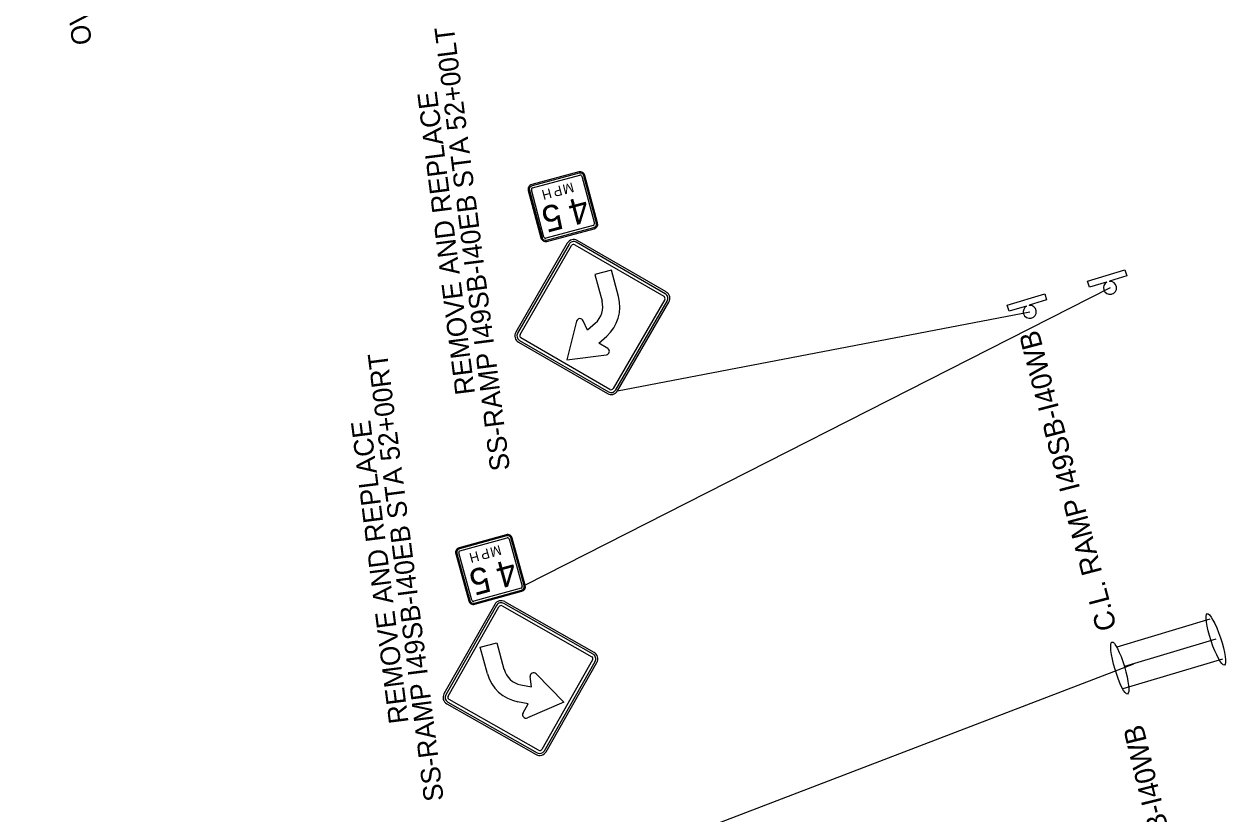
# Model space of a CAD drawing. Extents: x 639753 to 654136, y 407791 to 434220.
# Drawn here: x 643579 to 644317, y 427561 to 428045 of the extents above; entities that cross this region are included whole.
import ezdxf

# ---------------------------------------------------------------- set-up
doc = ezdxf.new("R2010")
doc.units = 0
for name, color, linetype in [('C-TRAF-SYMB', 7, 'Continuous'), ('R_Anno_Text', 7, 'Continuous'), ('R_Draft', 7, 'Continuous'), ('S_SIGN', 7, 'Continuous')]:
    doc.layers.add(name, color=color, linetype=linetype)

msp = doc.modelspace()

# ---------------------------------------------------------------- linework, layer by layer
at = {"layer": 'C-TRAF-SYMB'}
for p, q in [((644231.04, 427887.93), (644254.02, 427894.85)), ((644254.02, 427894.85), (644255.18, 427891.02)), ((644232.2, 427884.1), (644231.04, 427887.93)), ((644242.77, 427887.28), (644232.2, 427884.1)), ((644242.8, 427887.17), (644242.77, 427887.28)), ((644255.18, 427891.02), (644244.5, 427887.8)), ((644244.5, 427887.8), (644244.53, 427887.71)), ((644181.86, 427873.21), (644204.84, 427880.13)), ((644204.84, 427880.13), (644205.99, 427876.3)), ((644183.01, 427869.38), (644181.86, 427873.21)), ((644193.58, 427872.56), (644183.01, 427869.38)), ((644193.62, 427872.45), (644193.58, 427872.56)), ((644205.99, 427876.3), (644195.32, 427873.08)), ((644195.32, 427873.08), (644195.35, 427872.99)), ((644305.99, 427680.53), (644248.98, 427663.47)), ((644309.66, 427668.26), (644253.68, 427651.51)), ((644313.83, 427656.15), (644252.65, 427637.84))]:
    msp.add_line(p, q, dxfattribs=at)
for centre, start, end in [((644244.84, 427883.73), 120.62154, 196.75942), ((644244.84, 427883.73), 196.75942, 94.43951), ((644195.65, 427869.01), 120.62154, 196.75942), ((644195.65, 427869.01), 196.75942, 94.43951)]:
    msp.add_arc(centre, 4, start, end, dxfattribs=at)
for centre, major_axis in [((644309.66, 427668.26), (5.27, -15.78)), ((644250.81, 427650.65), (4.77, -15.94))]:
    msp.add_ellipse(centre, major_axis=major_axis, ratio=0.180134, dxfattribs=at)
at = {"layer": 'S_SIGN'}
for p, q in [((643919.39, 427954.76), (643890.41, 427947.03)), ((643930.79, 427923.64), (643923.06, 427952.63)), ((643888.28, 427943.35), (643896.01, 427914.37)), ((643899.68, 427912.24), (643928.67, 427919.97)), ((643912.21, 427911.11), (643880.65, 427856.59)), ((643972.88, 427881.19), (643918.36, 427912.75)), ((643939.32, 427894.57), (643929.18, 427891.86)), ((643943.65, 427878.33), (643939.32, 427894.57)), ((643929.18, 427891.86), (643933.51, 427875.62)), ((644244.84, 427883.73), (643886.49, 427701.37)), ((643942.96, 427820.52), (643974.52, 427875.04)), ((643917.94, 427863.25), (643912.04, 427839.67)), ((643924.52, 427857.72), (643921.95, 427863.59)), ((643942.96, 427820.52), (644195.65, 427869.01)), ((643929.41, 427862.03), (643924.52, 427857.72)), ((643882.29, 427850.44), (643936.81, 427818.88)), ((643931.48, 427849.85), (643936.36, 427854.17)), ((643936.99, 427846.58), (643931.48, 427849.85)), ((643912.04, 427839.67), (643936.16, 427842.64)), ((643874.83, 427732.39), (643845.91, 427724.42)), ((643886.49, 427701.37), (643878.52, 427730.29)), ((643843.82, 427720.73), (643851.79, 427691.81)), ((643855.47, 427689.71), (643884.4, 427697.68)), ((643867.75, 427689.65), (643836.64, 427634.87)), ((643928.67, 427660.23), (643873.88, 427691.34)), ((643858.84, 427663.37), (643868.97, 427666.16)), ((643868.97, 427666.16), (643873.43, 427649.96)), ((643863.31, 427647.17), (643858.84, 427663.37)), ((643899.24, 427599.31), (643930.36, 427654.09)), ((643997.17, 427552.78), (644259.53, 427653.26)), ((643890.23, 427639.04), (643889.48, 427645.4)), ((643893.11, 427647.14), (643910.12, 427629.77)), ((643883.83, 427640.3), (643890.23, 427639.04)), ((643838.33, 427628.73), (643893.11, 427597.62)), ((643888.2, 427628.74), (643881.8, 427630)), ((643885.09, 427623.13), (643888.2, 427628.74)), ((643910.12, 427629.77), (643887.79, 427620.15))]:
    msp.add_line(p, q, dxfattribs=at)
for points in [[(643919.59, 427954.03), (643890.6, 427946.3)], [(643890.92, 427945.09), (643919.91, 427952.82)], [(643919.59, 427954.03), (643919.59, 427954.03), (643919.59, 427954.03)], [(643921.13, 427952.11), (643928.86, 427923.13)], [(643930.07, 427923.45), (643922.34, 427952.44)], [(643889, 427943.55), (643896.73, 427914.56)], [(643889, 427943.55), (643889, 427943.55), (643889, 427943.55)], [(643897.94, 427914.88), (643890.21, 427943.87)], [(643930.07, 427923.45), (643930.07, 427923.45), (643930.07, 427923.45)], [(643928.15, 427921.9), (643899.17, 427914.17)], [(643899.49, 427912.97), (643928.47, 427920.7)], [(643913.29, 427910.49), (643881.73, 427855.97)], [(643883.24, 427855.09), (643914.81, 427909.61)], [(643899.49, 427912.97), (643899.49, 427912.97), (643899.49, 427912.97)], [(643913.29, 427910.49), (643913.29, 427910.49), (643913.29, 427910.49)], [(643916.86, 427910.16), (643971.38, 427878.59)], [(643972.26, 427880.1), (643917.73, 427911.67)], [(643972.26, 427880.1), (643972.26, 427880.1), (643972.26, 427880.1)], [(643971.93, 427876.54), (643940.36, 427822.02)], [(643941.87, 427821.14), (643973.44, 427875.66)], [(643882.91, 427851.53), (643937.43, 427819.96)], [(643882.91, 427851.53), (643882.91, 427851.53), (643882.91, 427851.53)], [(643938.31, 427821.47), (643883.79, 427853.04)], [(643941.87, 427821.14), (643941.87, 427821.14), (643941.87, 427821.14)], [(643875.03, 427731.66), (643846.11, 427723.69)], [(643846.44, 427722.49), (643875.36, 427730.46)], [(643875.03, 427731.66), (643875.03, 427731.66), (643875.03, 427731.66)], [(643876.59, 427729.76), (643884.56, 427700.84)], [(643885.77, 427701.17), (643877.8, 427730.09)], [(643844.54, 427720.93), (643852.51, 427692)], [(643844.54, 427720.93), (643844.54, 427720.93), (643844.54, 427720.93)], [(643853.71, 427692.34), (643845.74, 427721.26)], [(643885.77, 427701.17), (643885.77, 427701.17), (643885.77, 427701.17)], [(643883.87, 427699.61), (643854.94, 427691.64)], [(643855.28, 427690.43), (643884.2, 427698.4)], [(643868.84, 427689.03), (643837.72, 427634.25)], [(643839.25, 427633.39), (643870.36, 427688.17)], [(643855.28, 427690.43), (643855.28, 427690.43), (643855.28, 427690.43)], [(643868.84, 427689.03), (643868.84, 427689.03), (643868.84, 427689.03)], [(643872.4, 427688.73), (643927.18, 427657.62)], [(643928.05, 427659.14), (643873.27, 427690.25)], [(643928.05, 427659.14), (643928.05, 427659.14), (643928.05, 427659.14)], [(643927.75, 427655.58), (643896.63, 427600.79)], [(643898.16, 427599.93), (643929.27, 427654.71)], [(643838.94, 427629.82), (643893.73, 427598.71)], [(643838.94, 427629.82), (643838.94, 427629.82), (643838.94, 427629.82)], [(643894.59, 427600.23), (643839.81, 427631.34)], [(643898.16, 427599.93), (643898.16, 427599.93), (643898.16, 427599.93)]]:
    msp.add_lwpolyline(points, dxfattribs=at)
for centre, radius, start, end in [((643920.17, 427951.86), 3, 14.93017, 104.93038), ((643920.17, 427951.86), 2.25, 14.93017, 104.93038), ((643920.17, 427951.86), 1, 14.93017, 104.93038), ((643891.18, 427944.13), 3, 104.93038, 194.93059), ((643891.18, 427944.13), 2.25, 104.93038, 194.93059), ((643891.18, 427944.13), 1, 104.93038, 194.93059), ((643927.89, 427922.87), 1, 284.93053, 14.93017), ((643927.89, 427922.87), 2.25, 284.93053, 14.93017), ((643927.89, 427922.87), 3, 284.93053, 14.93017), ((643898.91, 427915.14), 1, 194.93032, 284.93053), ((643898.91, 427915.14), 3, 194.93032, 284.93053), ((643898.91, 427915.14), 2.25, 194.93032, 284.93053), ((643916.11, 427908.86), 4.5, 59.93027, 149.93048), ((643916.11, 427908.86), 3.25, 59.93027, 149.93048), ((643916.11, 427908.86), 1.5, 59.93027, 149.93048), ((643920.46, 427872.15), 24, 311.48598, 14.93017), ((643970.63, 427877.29), 1.5, 329.93006, 59.93027), ((643970.63, 427877.29), 3.25, 329.93006, 59.93027), ((643970.63, 427877.29), 4.5, 329.93006, 59.93027), ((643920.46, 427872.15), 13.5, 311.48598, 14.93017), ((643920.01, 427862.73), 2.13, 23.65803, 165.9372), ((643884.54, 427854.34), 4.5, 149.93048, 239.93012), ((643884.54, 427854.34), 3.25, 149.93048, 239.93012), ((643884.54, 427854.34), 1.5, 149.93048, 239.93012), ((643935.9, 427844.75), 2.13, 277.0346, 59.31377), ((643939.06, 427822.77), 4.5, 239.93031, 329.93006), ((643939.06, 427822.77), 3.25, 239.93031, 329.93006), ((643939.06, 427822.77), 1.5, 239.93031, 329.93006), ((643875.63, 427729.49), 3, 15.40548, 105.40569), ((643875.63, 427729.49), 2.25, 15.40548, 105.40569), ((643875.63, 427729.49), 1, 15.40548, 105.40569), ((643846.71, 427721.52), 3, 105.40569, 195.4059), ((643846.71, 427721.52), 2.25, 105.40569, 195.4059), ((643846.71, 427721.52), 1, 105.40569, 195.4059), ((643883.6, 427700.57), 2.25, 285.40584, 15.40548), ((643883.6, 427700.57), 3, 285.40584, 15.40548), ((643883.6, 427700.57), 1, 285.40584, 15.40548), ((643854.68, 427692.6), 3, 195.40563, 285.40584), ((643854.68, 427692.6), 2.25, 195.40563, 285.40584), ((643854.68, 427692.6), 1, 195.40563, 285.40584), ((643871.66, 427687.43), 4.5, 60.40558, 150.40579), ((643871.66, 427687.43), 3.25, 60.40558, 150.40579), ((643871.66, 427687.43), 1.5, 60.40558, 150.40579), ((643926.44, 427656.32), 1.5, 330.40537, 60.40558), ((643926.44, 427656.32), 3.25, 330.40537, 60.40558), ((643926.44, 427656.32), 4.5, 330.40537, 60.40558), ((643886.45, 427653.54), 13.5, 195.4059, 258.85009), ((643886.45, 427653.54), 24, 195.4059, 258.85009), ((643891.59, 427645.65), 2.13, 44.39886, 186.67803), ((643840.55, 427632.65), 4.5, 150.40579, 240.40543), ((643840.55, 427632.65), 3.25, 150.40579, 240.40543), ((643840.55, 427632.65), 1.5, 150.40579, 240.40543), ((643886.95, 427622.1), 2.13, 151.02229, 293.30147), ((643895.33, 427601.53), 4.5, 240.40562, 330.40537), ((643895.33, 427601.53), 3.25, 240.40562, 330.40537), ((643895.33, 427601.53), 1.5, 240.40562, 330.40537)]:
    msp.add_arc(centre, radius, start, end, dxfattribs=at)

# ---------------------------------------------------------------- texts
at = {"layer": 'R_Anno_Text'}
for s, p in [('OVERHEAD SIGN STRUCTURE', (643620.88, 428033.38)), ('SS-RAMP I49SB-I40EB STA 52+00LT', (643877.11, 427772.32)), ('REMOVE AND REPLACE', (643855.67, 427818.92)), ('SS-RAMP I49SB-I40EB STA 52+00RT', (643836.53, 427569.7)), ('REMOVE AND REPLACE', (643814.97, 427617.3))]:
    msp.add_text(s, height=12, rotation=97.22045, dxfattribs=at).set_placement(p)
at = {"layer": 'R_Draft'}
for rotation, p in [(104.71099, (644249.04, 427675.24)), (103.88239, (644310.31, 427432.76))]:
    msp.add_text('C.L. RAMP I49SB-I40WB', height=12.5, rotation=rotation, dxfattribs=at).set_placement(p)
at = {"layer": 'S_SIGN'}
for s, height, rotation, p in [('H', 6, 194.93032, (643901.68, 427944.86)), ('P', 6, 194.93032, (643908.14, 427946.58)), ('M', 6, 194.93032, (643915.31, 427948.49)), ('4', 16, 194.93032, (643923.08, 427940.21)), ('5', 16, 194.93032, (643906.77, 427935.87)), ('P', 6, 195.40563, (643863.64, 427724.12)), ('M', 6, 195.40563, (643870.81, 427726.09)), ('H', 6, 195.40563, (643857.2, 427722.34)), ('4', 16, 195.40563, (643878.64, 427717.88)), ('5', 16, 195.40563, (643862.37, 427713.39))]:
    msp.add_text(s, height=height, rotation=rotation, dxfattribs=at).set_placement(p)

doc.saveas('drawing.dxf')
